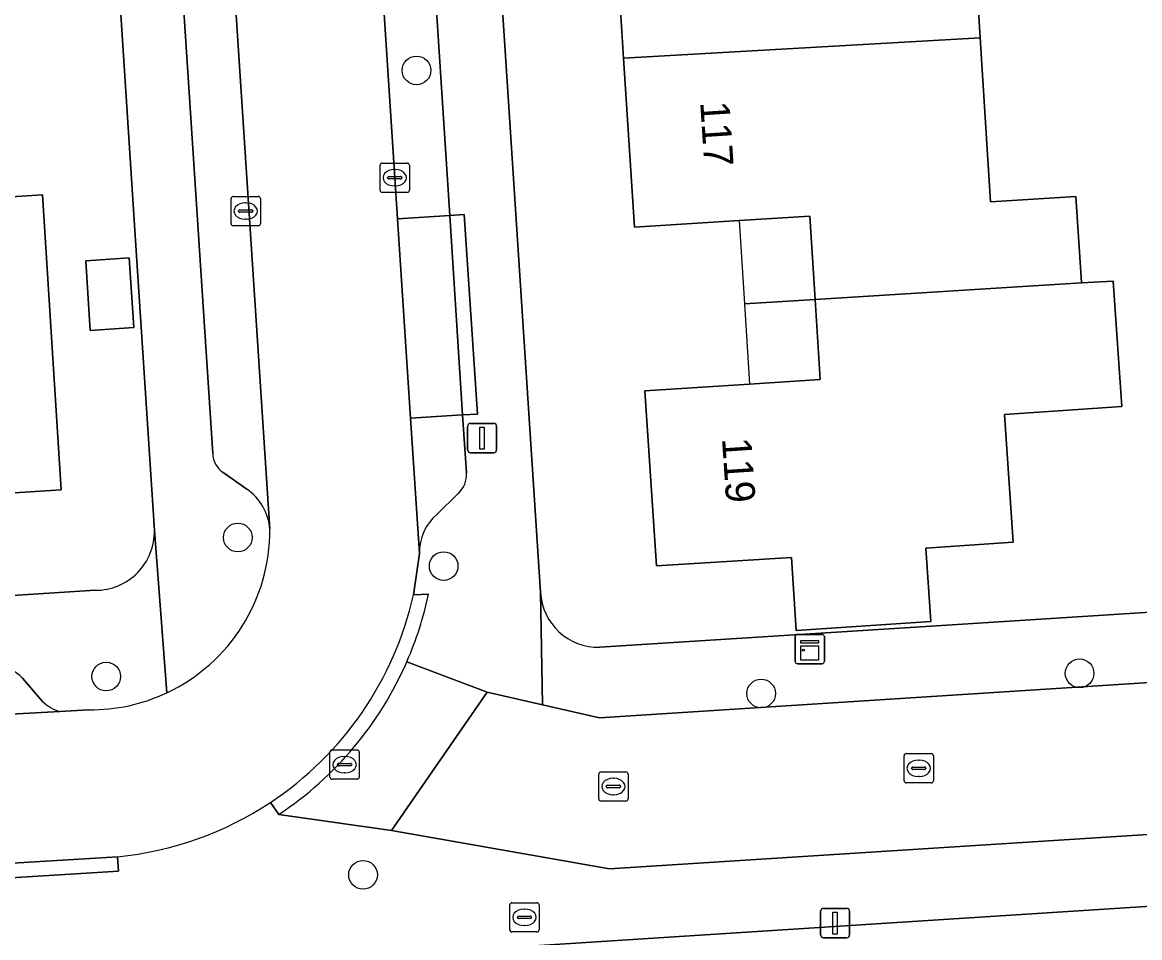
# Model space of a CAD drawing. Extents: x 159626 to 160723, y 388173 to 389416.
# Drawn here: x 160352.44 to 160390.58, y 388412.04 to 388443.29 of the extents above; entities that cross this region are included whole.
import ezdxf

# ---------------------------------------------------------------- set-up
doc = ezdxf.new("R2010")
doc.units = 0
for name, color, linetype in [('IMGEO_Boom', 7, 'Continuous'), ('IMGEO_Brandkraan', 7, 'Continuous'), ('IMGEO_Erf', 7, 'Continuous'), ('IMGEO_Kast', 7, 'Continuous'), ('IMGEO_Kolk', 7, 'Continuous'), ('IMGEO_Lichtmast', 7, 'Continuous'), ('IMGEO_Muur', 7, 'Continuous'), ('IMGEO_Pand', 7, 'Continuous'), ('IMGEO_Pand_nummerreeks', 7, 'Continuous'), ('IMGEO_Pand_overbouw', 7, 'Continuous'), ('IMGEO_Parkeervlak_open', 7, 'Continuous'), ('IMGEO_Rijbaan_lokaal_open', 7, 'Continuous'), ('IMGEO_Rioolput', 7, 'Continuous'), ('IMGEO_Voetpad_open', 7, 'Continuous')]:
    doc.layers.add(name, color=color, linetype=linetype)

msp = doc.modelspace()

# ---------------------------------------------------------------- linework, layer by layer
at = {"layer": 'IMGEO_Boom'}
for centre in [(160365.891, 388441.646), (160359.793, 388425.7), (160366.819, 388424.724), (160355.299, 388420.954), (160388.527, 388421.064), (160377.658, 388420.374), (160364.066, 388414.184)]:
    msp.add_circle(centre, 0.489, dxfattribs=at)
at = {"layer": 'IMGEO_Brandkraan'}
for p, q in [((160369.151, 388413.233), (160370.003, 388413.233)), ((160369.076, 388412.307), (160369.076, 388413.159)), ((160369.564, 388413.013), (160369.589, 388413.013)), ((160370.077, 388413.159), (160370.077, 388412.307)), ((160369.335, 388412.727), (160369.335, 388412.739)), ((160369.773, 388412.69), (160369.375, 388412.69)), ((160369.378, 388412.776), (160369.776, 388412.776)), ((160369.587, 388412.453), (160369.562, 388412.453)), ((160369.819, 388412.739), (160369.819, 388412.727)), ((160370.003, 388412.233), (160369.151, 388412.233))]:
    msp.add_line(p, q, dxfattribs=at)
for points in [[(160369.151, 388413.233), (160370.003, 388413.233)], [(160369.076, 388412.307), (160369.076, 388413.159)], [(160370.077, 388413.159), (160370.077, 388412.307)], [(160370.003, 388412.233), (160369.151, 388412.233)]]:
    msp.add_lwpolyline(points, dxfattribs=at)
for centre, radius, start, end in [((160369.153, 388413.157), 0.0765, 91.552, 178.448), ((160369.153, 388413.157), 0.0765, 91.552, 178.448), ((160370.001, 388413.157), 0.0765, 1.552, 88.448), ((160370.001, 388413.157), 0.0765, 1.552, 88.448), ((160369.375, 388412.736), 0.0403, 85.8775, 175.7526), ((160369.372, 388412.726), 0.0366, 178.938, 274.7102), ((160369.776, 388412.733), 0.043, 264.8664, 352.4533), ((160369.78, 388412.738), 0.0386, 1.7309, 96.639), ((160369.153, 388412.309), 0.0765, 181.552, 268.448), ((160369.153, 388412.309), 0.0765, 181.552, 268.448), ((160370.001, 388412.309), 0.0765, 271.552, 358.448), ((160370.001, 388412.309), 0.0765, 271.552, 358.448)]:
    msp.add_arc(centre, radius, start, end, dxfattribs=at)
for centre, major_axis, ratio, start_param, end_param in [((160369.563, 388412.733), (-0.387, 0.002), 0.722429, 4.712389, 7.853982), ((160369.588, 388412.733), (-0.39, 0.002), 0.717154, 1.570796, 4.712389)]:
    msp.add_ellipse(centre, major_axis=major_axis, ratio=ratio, start_param=start_param, end_param=end_param, dxfattribs=at)
at = {"layer": 'IMGEO_Erf'}
for points in [[(160366.464, 388479.982), (160370.129, 388423.835)], [(160372.154, 388421.957), (160383.458, 388422.677), (160397.71, 388423.584), (160434.858, 388425.95), (160434.196, 388436.021), (160431.43, 388478.134)], [(160356.946, 388425.941), (160356.336, 388435.32), (160354.748, 388459.708), (160354.228, 388467.691)], [(160329.438, 388452.712), (160324.422, 388452.395), (160324.952, 388444.008), (160318.839, 388443.623), (160318.31, 388452.009), (160313.294, 388451.693), (160313.823, 388443.306), (160307.71, 388442.92), (160308.212, 388433.506), (160308.484, 388429.388), (160309.04, 388420.951), (160354.932, 388423.897)], [(160384.765, 388448.618), (160385.136, 388442.758), (160385.491, 388437.159), (160388.403, 388437.344), (160388.579, 388434.586), (160388.591, 388434.39), (160389.679, 388434.457), (160389.969, 388430.169), (160385.968, 388429.897), (160386.263, 388425.536), (160383.279, 388425.333), (160383.447, 388422.838), (160378.857, 388422.527), (160378.688, 388425.021), (160374.087, 388424.728), (160373.682, 388430.706), (160377.26, 388430.935), (160379.674, 388431.089), (160379.499, 388433.83), (160379.318, 388436.672), (160376.904, 388436.518), (160373.328, 388436.29), (160372.96, 388442.061), (160372.773, 388444.989)], [(160347.635, 388437.043), (160353.12, 388437.4), (160353.76, 388427.33), (160348.057, 388426.962)], [(160407.747, 388408.996), (160407.414, 388414.173), (160365.311, 388411.469)]]:
    msp.add_lwpolyline(points, dxfattribs=at)
msp.add_lwpolyline([(160354.6, 388435.151), (160356.088, 388435.245), (160356.239, 388432.864), (160354.751, 388432.769)], close=True, dxfattribs=at)
for centre, radius, start, end in [((160354.927, 388425.917), 2.02, 270.1559, 0.6913), ((160372.09, 388423.919), 1.963, 182.4512, 271.8627)]:
    msp.add_arc(centre, radius, start, end, dxfattribs=at)
at = {"layer": 'IMGEO_Kast'}
for p, q in [((160378.892, 388422.391), (160379.733, 388422.391)), ((160379.733, 388422.391), (160378.892, 388422.391)), ((160378.817, 388421.466), (160378.817, 388422.307)), ((160378.817, 388422.307), (160378.817, 388421.466)), ((160379.817, 388422.316), (160379.817, 388421.475)), ((160379.817, 388421.475), (160379.817, 388422.316)), ((160379.742, 388421.391), (160378.901, 388421.391)), ((160378.901, 388421.391), (160379.742, 388421.391))]:
    msp.add_line(p, q, dxfattribs=at)
for points in [[(160379.012, 388422.181), (160379.612, 388422.181), (160379.612, 388422.096), (160379.012, 388422.096), (160379.012, 388422.181)], [(160379.012, 388422.006), (160379.612, 388422.006), (160379.612, 388421.517), (160379.012, 388421.517), (160379.012, 388422.006)]]:
    msp.add_lwpolyline(points, dxfattribs=at)
msp.add_circle((160379.096, 388421.855), 0.0377, dxfattribs=at)
for centre, start, end in [((160378.895, 388422.313), 92.4484, 184.2845), ((160378.895, 388422.313), 92.4484, 184.2845), ((160379.739, 388422.313), 2.4484, 94.2845), ((160379.739, 388422.313), 2.4484, 94.2845), ((160378.895, 388421.469), 182.4484, 274.2845), ((160378.895, 388421.469), 182.4484, 274.2845), ((160379.739, 388421.469), 272.4484, 4.2845), ((160379.739, 388421.469), 272.4484, 4.2845)]:
    msp.add_arc(centre, 0.0779, start, end, dxfattribs=at)
at = {"layer": 'IMGEO_Kolk'}
for p, q in [((160364.648, 388437.557), (160364.648, 388438.409)), ((160364.723, 388438.483), (160365.575, 388438.483)), ((160365.649, 388438.409), (160365.649, 388437.557)), ((160364.907, 388437.977), (160364.907, 388437.989)), ((160364.95, 388438.026), (160365.348, 388438.026)), ((160365.136, 388438.263), (160365.161, 388438.263)), ((160365.391, 388437.989), (160365.391, 388437.977)), ((160365.345, 388437.94), (160364.947, 388437.94)), ((160365.159, 388437.703), (160365.134, 388437.703)), ((160359.561, 388436.419), (160359.561, 388437.271)), ((160359.636, 388437.345), (160360.488, 388437.345)), ((160360.562, 388437.271), (160360.562, 388436.419)), ((160365.575, 388437.483), (160364.723, 388437.483)), ((160359.82, 388436.839), (160359.82, 388436.851)), ((160359.863, 388436.888), (160360.261, 388436.888)), ((160360.049, 388437.125), (160360.074, 388437.125)), ((160360.304, 388436.851), (160360.304, 388436.839)), ((160360.258, 388436.802), (160359.86, 388436.802)), ((160360.072, 388436.565), (160360.047, 388436.565)), ((160360.488, 388436.345), (160359.636, 388436.345)), ((160382.536, 388417.395), (160382.536, 388418.247)), ((160382.611, 388418.321), (160383.463, 388418.321)), ((160383.537, 388418.247), (160383.537, 388417.395)), ((160382.795, 388417.815), (160382.795, 388417.827)), ((160383.233, 388417.778), (160382.835, 388417.778)), ((160382.838, 388417.864), (160383.236, 388417.864)), ((160383.024, 388418.101), (160383.049, 388418.101)), ((160383.279, 388417.827), (160383.279, 388417.815)), ((160372.113, 388416.774), (160372.113, 388417.626)), ((160372.188, 388417.7), (160373.04, 388417.7)), ((160372.601, 388417.48), (160372.626, 388417.48)), ((160373.114, 388417.626), (160373.114, 388416.774)), ((160383.047, 388417.541), (160383.022, 388417.541)), ((160372.372, 388417.194), (160372.372, 388417.206)), ((160372.81, 388417.157), (160372.412, 388417.157)), ((160372.415, 388417.243), (160372.813, 388417.243)), ((160372.856, 388417.206), (160372.856, 388417.194)), ((160383.463, 388417.321), (160382.611, 388417.321)), ((160373.04, 388416.7), (160372.188, 388416.7)), ((160372.624, 388416.92), (160372.599, 388416.92))]:
    msp.add_line(p, q, dxfattribs=at)
for points in [[(160364.648, 388437.557), (160364.648, 388438.409)], [(160364.723, 388438.483), (160365.575, 388438.483)], [(160365.649, 388438.409), (160365.649, 388437.557)], [(160359.561, 388436.419), (160359.561, 388437.271)], [(160359.636, 388437.345), (160360.488, 388437.345)], [(160360.562, 388437.271), (160360.562, 388436.419)], [(160365.575, 388437.483), (160364.723, 388437.483)], [(160360.488, 388436.345), (160359.636, 388436.345)], [(160382.536, 388417.395), (160382.536, 388418.247)], [(160382.611, 388418.321), (160383.463, 388418.321)], [(160383.537, 388418.247), (160383.537, 388417.395)], [(160372.113, 388416.774), (160372.113, 388417.626)], [(160372.188, 388417.7), (160373.04, 388417.7)], [(160373.114, 388417.626), (160373.114, 388416.774)], [(160383.463, 388417.321), (160382.611, 388417.321)], [(160373.04, 388416.7), (160372.188, 388416.7)]]:
    msp.add_lwpolyline(points, dxfattribs=at)
for centre, radius, start, end in [((160364.725, 388438.407), 0.0765, 91.552, 178.448), ((160364.725, 388438.407), 0.0765, 91.552, 178.448), ((160365.573, 388438.407), 0.0765, 1.552, 88.448), ((160365.573, 388438.407), 0.0765, 1.552, 88.448), ((160364.947, 388437.986), 0.0403, 85.8775, 175.7526), ((160365.352, 388437.988), 0.0386, 1.7309, 96.639), ((160364.944, 388437.976), 0.0366, 178.938, 274.7102), ((160365.348, 388437.983), 0.043, 264.8664, 352.4533), ((160359.638, 388437.269), 0.0765, 91.552, 178.448), ((160359.638, 388437.269), 0.0765, 91.552, 178.448), ((160360.486, 388437.269), 0.0765, 1.552, 88.448), ((160360.486, 388437.269), 0.0765, 1.552, 88.448), ((160364.725, 388437.559), 0.0765, 181.552, 268.448), ((160364.725, 388437.559), 0.0765, 181.552, 268.448), ((160365.573, 388437.559), 0.0765, 271.552, 358.448), ((160365.573, 388437.559), 0.0765, 271.552, 358.448), ((160359.86, 388436.848), 0.0403, 85.8775, 175.7526), ((160359.857, 388436.838), 0.0366, 178.938, 274.7102), ((160360.261, 388436.845), 0.043, 264.8664, 352.4533), ((160360.265, 388436.85), 0.0386, 1.7309, 96.639), ((160359.638, 388436.421), 0.0765, 181.552, 268.448), ((160359.638, 388436.421), 0.0765, 181.552, 268.448), ((160360.486, 388436.421), 0.0765, 271.552, 358.448), ((160360.486, 388436.421), 0.0765, 271.552, 358.448), ((160382.613, 388418.245), 0.0765, 91.552, 178.448), ((160382.613, 388418.245), 0.0765, 91.552, 178.448), ((160383.461, 388418.245), 0.0765, 1.552, 88.448), ((160383.461, 388418.245), 0.0765, 1.552, 88.448), ((160382.835, 388417.824), 0.0403, 85.8775, 175.7526), ((160382.832, 388417.814), 0.0366, 178.938, 274.7102), ((160383.236, 388417.821), 0.043, 264.8664, 352.4533), ((160383.24, 388417.826), 0.0386, 1.7309, 96.639), ((160372.19, 388417.624), 0.0765, 91.552, 178.448), ((160372.19, 388417.624), 0.0765, 91.552, 178.448), ((160373.038, 388417.624), 0.0765, 1.552, 88.448), ((160373.038, 388417.624), 0.0765, 1.552, 88.448), ((160382.613, 388417.397), 0.0765, 181.552, 268.448), ((160382.613, 388417.397), 0.0765, 181.552, 268.448), ((160383.461, 388417.397), 0.0765, 271.552, 358.448), ((160383.461, 388417.397), 0.0765, 271.552, 358.448), ((160372.412, 388417.203), 0.0403, 85.8775, 175.7526), ((160372.409, 388417.193), 0.0366, 178.938, 274.7102), ((160372.813, 388417.2), 0.043, 264.8664, 352.4533), ((160372.817, 388417.205), 0.0386, 1.7309, 96.639), ((160372.19, 388416.776), 0.0765, 181.552, 268.448), ((160372.19, 388416.776), 0.0765, 181.552, 268.448), ((160373.038, 388416.776), 0.0765, 271.552, 358.448), ((160373.038, 388416.776), 0.0765, 271.552, 358.448)]:
    msp.add_arc(centre, radius, start, end, dxfattribs=at)
for centre, major_axis, ratio, start_param, end_param in [((160365.135, 388437.983), (-0.387, 0.002), 0.722429, 4.712389, 7.853982), ((160365.16, 388437.983), (-0.39, 0.002), 0.717154, 1.570796, 4.712389), ((160360.048, 388436.845), (-0.387, 0.002), 0.722429, 4.712389, 7.853982), ((160360.073, 388436.845), (-0.39, 0.002), 0.717154, 1.570796, 4.712389), ((160383.023, 388417.821), (-0.387, 0.002), 0.722429, 4.712389, 7.853982), ((160383.048, 388417.821), (-0.39, 0.002), 0.717154, 1.570796, 4.712389), ((160372.6, 388417.2), (-0.387, 0.002), 0.722429, 4.712389, 7.853982), ((160372.625, 388417.2), (-0.39, 0.002), 0.717154, 1.570796, 4.712389)]:
    msp.add_ellipse(centre, major_axis=major_axis, ratio=ratio, start_param=start_param, end_param=end_param, dxfattribs=at)
at = {"layer": 'IMGEO_Lichtmast'}
for p, q in [((160367.736, 388429.595), (160368.526, 388429.595)), ((160368.526, 388429.595), (160367.736, 388429.595)), ((160367.636, 388428.695), (160367.636, 388429.495)), ((160367.636, 388429.495), (160367.636, 388428.695)), ((160368.626, 388429.495), (160368.626, 388428.695)), ((160368.626, 388428.695), (160368.626, 388429.495)), ((160368.526, 388428.595), (160367.736, 388428.595)), ((160367.736, 388428.595), (160368.526, 388428.595)), ((160379.686, 388412.139), (160379.686, 388412.939)), ((160379.686, 388412.939), (160379.686, 388412.139)), ((160379.786, 388413.039), (160380.576, 388413.039)), ((160380.576, 388413.039), (160379.786, 388413.039)), ((160380.676, 388412.939), (160380.676, 388412.139)), ((160380.676, 388412.139), (160380.676, 388412.939)), ((160380.576, 388412.039), (160379.786, 388412.039)), ((160379.786, 388412.039), (160380.576, 388412.039))]:
    msp.add_line(p, q, dxfattribs=at)
for points in [[(160368.056, 388429.47), (160368.206, 388429.47), (160368.206, 388428.72), (160368.056, 388428.72), (160368.056, 388429.47)], [(160380.106, 388412.914), (160380.256, 388412.914), (160380.256, 388412.164), (160380.106, 388412.164), (160380.106, 388412.914)]]:
    msp.add_lwpolyline(points, dxfattribs=at)
for centre, start, end in [((160367.736, 388429.495), 90, 180), ((160367.736, 388429.495), 90, 180), ((160368.526, 388429.495), 0, 90), ((160368.526, 388429.495), 360, 90), ((160367.736, 388428.695), 180, 270), ((160367.736, 388428.695), 180, 270), ((160368.526, 388428.695), 270, 0), ((160368.526, 388428.695), 270, 0), ((160379.786, 388412.939), 90, 180), ((160379.786, 388412.939), 90, 180), ((160380.576, 388412.939), 0, 90), ((160380.576, 388412.939), 360, 90), ((160379.786, 388412.139), 180, 270), ((160379.786, 388412.139), 180, 270), ((160380.576, 388412.139), 270, 0), ((160380.576, 388412.139), 270, 0)]:
    msp.add_arc(centre, 0.1, start, end, dxfattribs=at)
at = {"layer": 'IMGEO_Muur'}
for points in [[(160356.336, 388435.32), (160354.748, 388459.708)], [(160397.71, 388423.584), (160383.458, 388422.677)]]:
    msp.add_lwpolyline(points, dxfattribs=at)
at = {"layer": 'IMGEO_Pand'}
for points in [[(160385.136, 388442.758), (160384.765, 388448.618), (160388.751, 388448.887), (160388.565, 388451.819), (160384.578, 388451.567), (160378.389, 388451.176), (160378.567, 388448.33), (160372.57, 388447.961), (160372.699, 388446.048), (160372.281, 388446.027), (160372.375, 388444.963), (160372.773, 388444.989), (160372.96, 388442.061)], [(160385.136, 388442.758), (160372.96, 388442.061), (160373.328, 388436.29), (160376.904, 388436.518), (160379.318, 388436.672), (160379.499, 388433.83), (160388.591, 388434.39), (160388.579, 388434.586), (160388.403, 388437.344), (160385.491, 388437.159)], [(160353.12, 388437.4), (160347.635, 388437.043), (160347.288, 388442.379), (160342.712, 388442.081), (160343.543, 388429.485), (160346.447, 388429.675), (160347.877, 388429.756), (160347.999, 388427.859), (160348.057, 388426.962), (160353.76, 388427.33)], [(160354.6, 388435.151), (160354.751, 388432.769), (160356.239, 388432.864), (160356.088, 388435.245)], [(160385.968, 388429.897), (160389.969, 388430.169), (160389.679, 388434.457), (160388.591, 388434.39), (160379.499, 388433.83), (160379.674, 388431.089), (160377.26, 388430.935), (160373.682, 388430.706), (160374.087, 388424.728), (160378.688, 388425.021), (160378.857, 388422.527), (160383.447, 388422.838), (160383.279, 388425.333), (160386.263, 388425.536)]]:
    msp.add_lwpolyline(points, close=True, dxfattribs=at)
at = {"layer": 'IMGEO_Pand_overbouw'}
for points in [[(160376.904, 388436.518), (160377.085, 388433.681), (160379.499, 388433.83), (160379.318, 388436.672)], [(160379.499, 388433.83), (160377.085, 388433.681), (160377.26, 388430.935), (160379.674, 388431.089)]]:
    msp.add_lwpolyline(points, close=True, dxfattribs=at)
at = {"layer": 'IMGEO_Parkeervlak_open'}
for points in [[(160360.883, 388425.982), (160358.43, 388463.522)], [(160356.822, 388460.691), (160357.092, 388456.697), (160358.936, 388428.569)], [(160367.466, 388429.884), (160365.692, 388429.772), (160365.996, 388425.154)], [(160367.594, 388427.904), (160367.466, 388429.884)], [(160359.293, 388427.919), (160360.095, 388427.353)], [(160366.594, 388426.494), (160367.314, 388427.197)], [(160351.465, 388421.405), (160346.871, 388421.112), (160346.984, 388419.361), (160350.168, 388419.566), (160353.713, 388419.763)], [(160353.128, 388420.103), (160352.436, 388420.899)]]:
    msp.add_lwpolyline(points, dxfattribs=at)
for points in [[(160366.377, 388446.676), (160364.589, 388446.558), (160365.245, 388436.577), (160367.026, 388436.694)], [(160367.026, 388436.694), (160365.245, 388436.577), (160365.692, 388429.772), (160367.466, 388429.884)]]:
    msp.add_lwpolyline(points, close=True, dxfattribs=at)
for centre, radius, start, end in [((160359.748, 388428.592), 0.813, 181.635, 235.9189), ((160366.733, 388427.836), 0.864, 312.2725, 4.5165), ((160359.08, 388425.857), 1.808, 3.9514, 55.826), ((160367.654, 388425.217), 1.66, 129.7132, 182.1873), ((160351.185, 388419.682), 1.746, 44.1965, 80.7543), ((160354.039, 388420.997), 1.276, 224.4605, 255.2095)]:
    msp.add_arc(centre, radius, start, end, dxfattribs=at)
at = {"layer": 'IMGEO_Rijbaan_lokaal_open'}
for points in [[(160364.342, 388450.32), (160363.877, 388457.381), (160363.266, 388467.074), (160358.219, 388466.756), (160358.43, 388463.522), (160360.883, 388425.982)], [(160365.785, 388423.742), (160365.996, 388425.154), (160365.692, 388429.772), (160365.245, 388436.577), (160364.589, 388446.558), (160364.342, 388450.32)], [(160354.7, 388419.818), (160353.713, 388419.763), (160350.168, 388419.566), (160346.984, 388419.361), (160340.983, 388418.975), (160326.417, 388418.038), (160326.895, 388412.979), (160330.603, 388413.217), (160337.388, 388413.652), (160348.89, 388414.389), (160354.934, 388414.748), (160355.689, 388414.804)]]:
    msp.add_lwpolyline(points, dxfattribs=at)
msp.add_lwpolyline([(160395.167, 388421.024), (160372.143, 388419.54), (160370.196, 388419.988), (160368.305, 388420.423), (160365.039, 388415.703), (160372.485, 388414.387), (160395.5, 388415.86)], close=True, dxfattribs=at)
for centre, radius, start, end in [((160354.772, 388425.93), 6.111, 295.1791, 0.4915), ((160354.544, 388426.26), 11.52, 303.5307, 347.3747), ((160354.772, 388425.923), 6.105, 269.3272, 295.2077), ((160354.574, 388426.217), 11.468, 275.58, 303.5216)]:
    msp.add_arc(centre, radius, start, end, dxfattribs=at)
at = {"layer": 'IMGEO_Rioolput'}
for p, q in [((160362.936, 388417.52), (160362.936, 388418.372)), ((160363.011, 388418.446), (160363.863, 388418.446)), ((160363.424, 388418.226), (160363.449, 388418.226)), ((160363.937, 388418.372), (160363.937, 388417.52)), ((160363.195, 388417.94), (160363.195, 388417.952)), ((160363.633, 388417.903), (160363.235, 388417.903)), ((160363.238, 388417.989), (160363.636, 388417.989)), ((160363.679, 388417.952), (160363.679, 388417.94)), ((160363.863, 388417.446), (160363.011, 388417.446)), ((160363.447, 388417.666), (160363.422, 388417.666))]:
    msp.add_line(p, q, dxfattribs=at)
for points in [[(160362.936, 388417.52), (160362.936, 388418.372)], [(160363.011, 388418.446), (160363.863, 388418.446)], [(160363.937, 388418.372), (160363.937, 388417.52)], [(160363.863, 388417.446), (160363.011, 388417.446)]]:
    msp.add_lwpolyline(points, dxfattribs=at)
for centre, radius, start, end in [((160363.013, 388418.37), 0.0765, 91.552, 178.448), ((160363.013, 388418.37), 0.0765, 91.552, 178.448), ((160363.861, 388418.37), 0.0765, 1.552, 88.448), ((160363.861, 388418.37), 0.0765, 1.552, 88.448), ((160363.235, 388417.949), 0.0403, 85.8775, 175.7526), ((160363.232, 388417.939), 0.0366, 178.938, 274.7102), ((160363.636, 388417.946), 0.043, 264.8664, 352.4533), ((160363.64, 388417.951), 0.0386, 1.7309, 96.639), ((160363.013, 388417.522), 0.0765, 181.552, 268.448), ((160363.013, 388417.522), 0.0765, 181.552, 268.448), ((160363.861, 388417.522), 0.0765, 271.552, 358.448), ((160363.861, 388417.522), 0.0765, 271.552, 358.448)]:
    msp.add_arc(centre, radius, start, end, dxfattribs=at)
for centre, major_axis, ratio, start_param, end_param in [((160363.423, 388417.946), (-0.387, 0.002), 0.722429, 4.712389, 7.853982), ((160363.448, 388417.946), (-0.39, 0.002), 0.717154, 1.570796, 4.712389)]:
    msp.add_ellipse(centre, major_axis=major_axis, ratio=ratio, start_param=start_param, end_param=end_param, dxfattribs=at)
at = {"layer": 'IMGEO_Voetpad_open'}
for points in [[(160365.565, 388421.461), (160368.305, 388420.423), (160370.196, 388419.988), (160370.129, 388423.835), (160366.464, 388479.982)], [(160364.415, 388477.386), (160365.049, 388467.186), (160365.661, 388457.518), (160366.133, 388450.431), (160366.632, 388450.462), (160366.868, 388446.706), (160366.377, 388446.676), (160367.026, 388436.694), (160367.524, 388436.726), (160367.97, 388429.916), (160367.466, 388429.884), (160367.594, 388427.904)], [(160355.011, 388469.847), (160354.802, 388469.835), (160354.095, 388469.795), (160354.228, 388467.691), (160354.748, 388459.708), (160356.336, 388435.32), (160356.946, 388425.941), (160357.372, 388420.399)], [(160358.936, 388428.569), (160357.092, 388456.697), (160356.822, 388460.691)], [(160360.095, 388427.353), (160359.293, 388427.919)], [(160367.314, 388427.197), (160366.594, 388426.494)], [(160442.523, 388424.077), (160444.954, 388424.235), (160444.802, 388426.589), (160434.858, 388425.95), (160397.71, 388423.584), (160383.458, 388422.677), (160372.154, 388421.957)], [(160357.372, 388420.399), (160356.946, 388425.941)], [(160365.996, 388425.154), (160365.785, 388423.742), (160366.301, 388423.761)], [(160354.932, 388423.897), (160309.04, 388420.951), (160306.551, 388420.791), (160304.711, 388420.673), (160302.262, 388420.517), (160257.994, 388417.701), (160222.442, 388415.483), (160220.47, 388415.355), (160220.535, 388414.375)], [(160370.129, 388423.835), (160370.196, 388419.988), (160372.143, 388419.54), (160395.167, 388421.024), (160397.911, 388421.201), (160442.523, 388424.077)], [(160366.301, 388423.761), (160365.785, 388423.742)], [(160368.305, 388420.423), (160365.565, 388421.461)], [(160352.436, 388420.899), (160353.128, 388420.103)], [(160361.193, 388416.247), (160365.039, 388415.703), (160368.305, 388420.423)], [(160353.713, 388419.763), (160354.7, 388419.818)], [(160407.414, 388414.173), (160408.955, 388414.272), (160433.731, 388415.864), (160436.718, 388416.064), (160433.903, 388418.319), (160398.244, 388416.036), (160395.5, 388415.86), (160372.485, 388414.387), (160365.039, 388415.703), (160361.193, 388416.247), (160360.907, 388416.657)], [(160360.907, 388416.657), (160361.193, 388416.247)], [(160355.689, 388414.804), (160355.719, 388414.305), (160348.92, 388413.89), (160348.89, 388414.389)], [(160263.264, 388405.642), (160268.623, 388405.331), (160359.06, 388411.068), (160365.311, 388411.469), (160407.414, 388414.173)]]:
    msp.add_lwpolyline(points, dxfattribs=at)
for points in [[(160367.026, 388436.694), (160367.466, 388429.884), (160367.97, 388429.916), (160367.524, 388436.726)], [(160348.89, 388414.389), (160348.92, 388413.89), (160355.719, 388414.305), (160355.689, 388414.804), (160354.934, 388414.748)]]:
    msp.add_lwpolyline(points, close=True, dxfattribs=at)
for centre, radius, start, end in [((160359.748, 388428.592), 0.813, 181.635, 235.9189), ((160366.733, 388427.836), 0.864, 312.2725, 4.5165), ((160359.08, 388425.857), 1.808, 3.9514, 55.826), ((160367.654, 388425.217), 1.66, 129.7132, 182.1873), ((160354.927, 388425.917), 2.02, 270.1559, 0.6913), ((160354.772, 388425.93), 6.111, 295.1791, 0.4915), ((160354.544, 388426.26), 11.52, 303.5307, 347.3747), ((160354.529, 388426.26), 12.034, 336.497, 348.0137), ((160354.529, 388426.26), 12.034, 336.497, 348.0137), ((160372.09, 388423.919), 1.963, 182.4512, 271.8627), ((160351.185, 388419.682), 1.746, 44.1965, 80.7543), ((160354.541, 388426.265), 12.025, 303.5852, 336.4544), ((160354.541, 388426.265), 12.025, 303.5852, 336.4544), ((160354.039, 388420.997), 1.276, 224.4605, 255.2095), ((160354.772, 388425.923), 6.105, 269.3272, 295.2077), ((160354.574, 388426.217), 11.468, 275.58, 303.5216)]:
    msp.add_arc(centre, radius, start, end, dxfattribs=at)

# ---------------------------------------------------------------- texts
at = {"layer": 'IMGEO_Pand_nummerreeks'}
for s, rotation, p in [('117', 273.7183, (160375.575, 388440.564)), ('119', 273.873, (160376.319, 388429.08))]:
    msp.add_text(s, height=1, rotation=rotation, dxfattribs=at).set_placement(p)

doc.saveas('drawing.dxf')
